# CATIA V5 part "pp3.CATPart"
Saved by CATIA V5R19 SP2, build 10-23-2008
Part number: pp3
Publications: "Line.1", "Line.2", "Line.3", "Plane.1", "Plane.2", "Line.4", "Point.1", "Point.2"
Bounding box of the stored display mesh (mm): x -10 to 0, y -110 to 100, z 0 to 50
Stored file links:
  C:\Users\Welcome\Documents\thinkm2\pp3.CATPart
  C:\Users\Welcome\Documents\thinkm2\Brasmeca.CATProduct
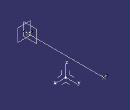
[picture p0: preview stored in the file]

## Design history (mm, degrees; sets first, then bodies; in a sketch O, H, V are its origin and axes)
AxisSystem1: origin (0, 0, 0), X (1, 0, 0), Y (0, 1, 0), Z (0, 0, 1)
Set1
  Point1: linked copy from another document
  Point2: linked copy from another document
Body1 (main body)
  Line1: type PtPt, FirstPoint Point1, SecondPoint Point2
  Line2: type PtDir, RefPoint Point1, Direction edge [XY plane of AxisSystem1 | ZX plane of AxisSystem1], Start 0, End -10
  Line3: type PtDir, RefPoint Point2, Direction edge [XY plane of AxisSystem1 | ZX plane of AxisSystem1], Start 0, End -10
  Plane1: type Normal, Curve Line3
  Line4: type PtDir, RefPoint Point2, Direction edge [YZ plane of AxisSystem1 | XY plane of AxisSystem1], Start 0, End -10
  Plane2: type Normal, Curve Line4, RefPoint vertex of Line4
